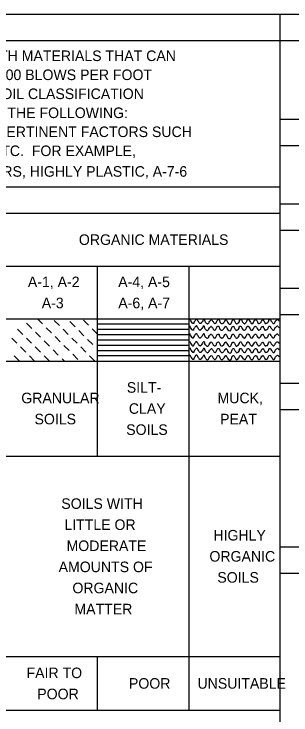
# Model space of a CAD drawing. Extents: x 278618 to 280654, y 171155 to 171855.
# Drawn here: x 280500.95 to 280512.35, y 171592.9 to 171621.7 of the extents above; entities that cross this region are included whole.
import ezdxf

# ---------------------------------------------------------------- set-up
doc = ezdxf.new("R2010")
doc.units = 0
doc.layers.add('Geotech Sheets and Borders Cell', color=7, linetype='Continuous')

msp = doc.modelspace()

# ---------------------------------------------------------------- linework, layer by layer
at = {"layer": 'Geotech Sheets and Borders Cell'}
for p, q in [((280474.148, 171621.702), (280624.148, 171621.702)), ((280511.888, 171621.702), (280511.888, 171541.488)), ((280474.148, 171620.618), (280624.148, 171620.618)), ((280549.148, 171617.364), (280511.888, 171617.364)), ((280549.148, 171616.28), (280511.888, 171616.28)), ((280474.148, 171614.6), (280511.888, 171614.6)), ((280549.148, 171613.894), (280511.888, 171613.894)), ((280474.148, 171613.515), (280511.888, 171613.515)), ((280549.148, 171612.809), (280511.888, 171612.809)), ((280474.148, 171611.346), (280511.888, 171611.346)), ((280504.384, 171603.538), (280504.384, 171611.346)), ((280508.158, 171593.093), (280508.158, 171611.346)), ((280549.148, 171610.423), (280511.888, 171610.423)), ((280549.148, 171609.339), (280511.888, 171609.339)), ((280474.148, 171609.177), (280511.888, 171609.177)), ((280501.677, 171608.782), (280501.464, 171608.995)), ((280501.907, 171609.177), (280502.119, 171608.965)), ((280502.813, 171608.899), (280502.601, 171609.112)), ((280503.247, 171609.06), (280503.46, 171608.847)), ((280504.015, 171608.912), (280503.802, 171609.125)), ((280501.308, 171608.535), (280501.095, 171608.748)), ((280502.271, 171608.813), (280502.483, 171608.6)), ((280503.178, 171608.535), (280502.965, 171608.748)), ((280503.611, 171608.696), (280503.824, 171608.483)), ((280504.379, 171608.548), (280504.167, 171608.761)), ((280504.384, 171608.965), (280508.158, 171608.965)), ((280504.384, 171608.748), (280508.158, 171608.748)), ((280508.184, 171608.895), (280508.179, 171608.891)), ((280502.041, 171608.418), (280501.828, 171608.631)), ((280502.635, 171608.448), (280502.848, 171608.236)), ((280504.384, 171608.531), (280508.158, 171608.531)), ((280508.184, 171608.574), (280508.179, 171608.57)), ((280501.065, 171608.171), (280500.852, 171608.383)), ((280501.672, 171608.171), (280501.46, 171608.383)), ((280502.193, 171608.266), (280502.405, 171608.054)), ((280503.542, 171608.171), (280503.329, 171608.383)), ((280503.976, 171608.331), (280504.188, 171608.119)), ((280504.384, 171608.314), (280508.158, 171608.314)), ((280508.188, 171608.249), (280508.184, 171608.244)), ((280501.429, 171607.806), (280501.217, 171608.019)), ((280502.037, 171607.806), (280501.824, 171608.019)), ((280502.557, 171607.902), (280502.77, 171607.689)), ((280503, 171608.084), (280503.212, 171607.871)), ((280503.906, 171607.806), (280503.694, 171608.019)), ((280504.384, 171608.097), (280508.158, 171608.097)), ((280504.384, 171607.88), (280508.158, 171607.88)), ((280508.197, 171607.98), (280508.192, 171607.975)), ((280501.16, 171607.446), (280500.948, 171607.659)), ((280501.794, 171607.442), (280501.581, 171607.654)), ((280502.401, 171607.442), (280502.188, 171607.654)), ((280502.922, 171607.537), (280503.021, 171607.442)), ((280503.364, 171607.72), (280503.577, 171607.507)), ((280504.271, 171607.442), (280504.058, 171607.654)), ((280504.384, 171607.663), (280508.158, 171607.663)), ((280508.162, 171607.62), (280508.158, 171607.624)), ((280508.166, 171607.663), (280508.162, 171607.659)), ((280508.192, 171607.694), (280508.188, 171607.689)), ((280474.148, 171607.442), (280511.888, 171607.442)), ((280549.148, 171606.519), (280511.888, 171606.519)), ((280549.148, 171605.435), (280511.888, 171605.435)), ((280474.148, 171603.538), (280511.888, 171603.538)), ((280549.148, 171599.795), (280511.888, 171599.795)), ((280549.148, 171598.711), (280511.888, 171598.711)), ((280474.148, 171595.296), (280511.888, 171595.296)), ((280504.384, 171593.093), (280504.384, 171595.296)), ((280474.148, 171593.093), (280511.888, 171593.093))]:
    msp.add_line(p, q, dxfattribs=at)
for points in [[(280508.86, 171608.999), (280508.834, 171609.034), (280508.804, 171609.108), (280508.787, 171609.151), (280508.769, 171609.155), (280508.748, 171609.142), (280508.717, 171609.095), (280508.656, 171609.008), (280508.635, 171608.986), (280508.609, 171608.978), (280508.591, 171608.986), (280508.574, 171609.008), (280508.5, 171609.129), (280508.483, 171609.151), (280508.474, 171609.155), (280508.453, 171609.155), (280508.427, 171609.138), (280508.392, 171609.082), (280508.348, 171609.008), (280508.344, 171608.986), (280508.318, 171608.978), (280508.296, 171608.991), (280508.283, 171609.017), (280508.231, 171609.095), (280508.192, 171609.164)], [(280508.865, 171608.999), (280508.895, 171608.973), (280508.956, 171608.995), (280508.986, 171609.043), (280509.047, 171609.125), (280509.073, 171609.147), (280509.108, 171609.112), (280509.138, 171609.06), (280509.173, 171609.008), (280509.207, 171608.982), (280509.251, 171608.995), (280509.285, 171609.047), (280509.351, 171609.142), (280509.385, 171609.142), (280509.411, 171609.099), (280509.481, 171608.986), (280509.515, 171608.982), (280509.55, 171608.995), (280509.65, 171609.125), (280509.676, 171609.147), (280509.689, 171609.125), (280509.715, 171609.086), (280509.767, 171608.995), (280509.854, 171608.96), (280509.884, 171608.986), (280509.945, 171609.121), (280509.993, 171609.142), (280510.01, 171609.121), (280510.071, 171609.017), (280510.105, 171608.973), (280510.162, 171608.995), (280510.222, 171609.069), (280510.257, 171609.142), (280510.288, 171609.147), (280510.322, 171609.108), (280510.374, 171609.017), (280510.422, 171608.986), (280510.452, 171608.973), (280510.496, 171609.03), (280510.535, 171609.086), (280510.561, 171609.142), (280510.6, 171609.147), (280510.622, 171609.125), (280510.678, 171609.034), (280510.713, 171608.986), (280510.773, 171608.986), (280510.825, 171609.073), (280510.878, 171609.134), (280510.895, 171609.147), (280510.938, 171609.112), (280510.969, 171609.047), (280511.021, 171608.986), (280511.064, 171608.995), (280511.116, 171609.043), (280511.168, 171609.125), (280511.19, 171609.134), (280511.203, 171609.142), (280511.22, 171609.112), (280511.242, 171609.073), (280511.311, 171608.986), (280511.329, 171608.995), (280511.359, 171608.995), (280511.433, 171609.108), (280511.459, 171609.147), (280511.511, 171609.142), (280511.524, 171609.099), (280511.572, 171609.043), (280511.619, 171608.986), (280511.65, 171608.986), (280511.684, 171609.021), (280511.715, 171609.095)], [(280511.715, 171609.095), (280511.762, 171609.134), (280511.802, 171609.155), (280511.836, 171609.125), (280511.862, 171609.086)], [(280508.847, 171608.726), (280508.821, 171608.761), (280508.791, 171608.834), (280508.774, 171608.878), (280508.756, 171608.882), (280508.735, 171608.869), (280508.704, 171608.821), (280508.643, 171608.735), (280508.622, 171608.713), (280508.596, 171608.704), (280508.578, 171608.713), (280508.561, 171608.735), (280508.487, 171608.856), (280508.47, 171608.878), (280508.461, 171608.882), (280508.44, 171608.882), (280508.414, 171608.865), (280508.379, 171608.808), (280508.335, 171608.735), (280508.331, 171608.713), (280508.305, 171608.704), (280508.283, 171608.717), (280508.27, 171608.743), (280508.218, 171608.821), (280508.179, 171608.891)], [(280508.852, 171608.726), (280508.882, 171608.7), (280508.943, 171608.722), (280508.973, 171608.769), (280509.034, 171608.852), (280509.06, 171608.873), (280509.095, 171608.839), (280509.125, 171608.787), (280509.16, 171608.735), (280509.194, 171608.709), (280509.238, 171608.722), (280509.272, 171608.774), (280509.338, 171608.869), (280509.372, 171608.869), (280509.398, 171608.826), (280509.468, 171608.713), (280509.502, 171608.709), (280509.537, 171608.722), (280509.637, 171608.852), (280509.663, 171608.873), (280509.676, 171608.852), (280509.702, 171608.813), (280509.754, 171608.722), (280509.841, 171608.687), (280509.871, 171608.713), (280509.932, 171608.847), (280509.98, 171608.869), (280509.997, 171608.847), (280510.058, 171608.743), (280510.092, 171608.7), (280510.149, 171608.722), (280510.209, 171608.795), (280510.244, 171608.869), (280510.275, 171608.873), (280510.309, 171608.834), (280510.361, 171608.743), (280510.409, 171608.713), (280510.439, 171608.7), (280510.483, 171608.756), (280510.522, 171608.813), (280510.548, 171608.869), (280510.587, 171608.873), (280510.609, 171608.852), (280510.665, 171608.761), (280510.7, 171608.713), (280510.76, 171608.713), (280510.812, 171608.8), (280510.864, 171608.86), (280510.882, 171608.873), (280510.925, 171608.839), (280510.956, 171608.774), (280511.008, 171608.713), (280511.051, 171608.722), (280511.103, 171608.769), (280511.155, 171608.852), (280511.177, 171608.86), (280511.19, 171608.869), (280511.207, 171608.839), (280511.229, 171608.8), (280511.298, 171608.713), (280511.316, 171608.722), (280511.346, 171608.722), (280511.42, 171608.834), (280511.446, 171608.873), (280511.498, 171608.869), (280511.511, 171608.826), (280511.559, 171608.769), (280511.606, 171608.713), (280511.637, 171608.713), (280511.671, 171608.748), (280511.702, 171608.821)], [(280511.702, 171608.821), (280511.749, 171608.86), (280511.788, 171608.882), (280511.823, 171608.852), (280511.849, 171608.813)], [(280508.847, 171608.405), (280508.821, 171608.44), (280508.791, 171608.513), (280508.774, 171608.557), (280508.756, 171608.561), (280508.735, 171608.548), (280508.704, 171608.5), (280508.643, 171608.414), (280508.622, 171608.392), (280508.596, 171608.383), (280508.578, 171608.392), (280508.561, 171608.414), (280508.487, 171608.535), (280508.47, 171608.557), (280508.461, 171608.561), (280508.44, 171608.561), (280508.414, 171608.544), (280508.379, 171608.487), (280508.335, 171608.414), (280508.331, 171608.392), (280508.305, 171608.383), (280508.283, 171608.396), (280508.27, 171608.422), (280508.218, 171608.5), (280508.179, 171608.57)], [(280508.852, 171608.405), (280508.882, 171608.379), (280508.943, 171608.401), (280508.973, 171608.448), (280509.034, 171608.531), (280509.06, 171608.552), (280509.095, 171608.518), (280509.125, 171608.466), (280509.16, 171608.414), (280509.194, 171608.388), (280509.238, 171608.401), (280509.272, 171608.453), (280509.338, 171608.548), (280509.372, 171608.548), (280509.398, 171608.505), (280509.468, 171608.392), (280509.502, 171608.388), (280509.537, 171608.401), (280509.637, 171608.531), (280509.663, 171608.552), (280509.676, 171608.531), (280509.702, 171608.492), (280509.754, 171608.401), (280509.841, 171608.366), (280509.871, 171608.392), (280509.932, 171608.526), (280509.98, 171608.548), (280509.997, 171608.526), (280510.058, 171608.422), (280510.092, 171608.379), (280510.149, 171608.401), (280510.209, 171608.474), (280510.244, 171608.548), (280510.275, 171608.552), (280510.309, 171608.513), (280510.361, 171608.422), (280510.409, 171608.392), (280510.439, 171608.379), (280510.483, 171608.435), (280510.522, 171608.492), (280510.548, 171608.548), (280510.587, 171608.552), (280510.609, 171608.531), (280510.665, 171608.44), (280510.7, 171608.392), (280510.76, 171608.392), (280510.812, 171608.479), (280510.864, 171608.539), (280510.882, 171608.552), (280510.925, 171608.518), (280510.956, 171608.453), (280511.008, 171608.392), (280511.051, 171608.401), (280511.103, 171608.448), (280511.155, 171608.531), (280511.177, 171608.539), (280511.19, 171608.548), (280511.207, 171608.518), (280511.229, 171608.479), (280511.298, 171608.392), (280511.316, 171608.401), (280511.346, 171608.401), (280511.42, 171608.513), (280511.446, 171608.552), (280511.498, 171608.548), (280511.511, 171608.505), (280511.559, 171608.448), (280511.606, 171608.392), (280511.637, 171608.392), (280511.671, 171608.427), (280511.702, 171608.5)], [(280511.702, 171608.5), (280511.749, 171608.539), (280511.788, 171608.561), (280511.823, 171608.531), (280511.849, 171608.492)], [(280508.852, 171608.08), (280508.826, 171608.114), (280508.795, 171608.188), (280508.778, 171608.231), (280508.761, 171608.236), (280508.739, 171608.223), (280508.709, 171608.175), (280508.648, 171608.088), (280508.626, 171608.067), (280508.6, 171608.058), (280508.583, 171608.067), (280508.565, 171608.088), (280508.492, 171608.21), (280508.474, 171608.231), (280508.466, 171608.236), (280508.444, 171608.236), (280508.418, 171608.218), (280508.383, 171608.162), (280508.34, 171608.088), (280508.335, 171608.067), (280508.309, 171608.058), (280508.288, 171608.071), (280508.275, 171608.097), (280508.223, 171608.175), (280508.184, 171608.244)], [(280508.856, 171608.08), (280508.886, 171608.054), (280508.947, 171608.075), (280508.977, 171608.123), (280509.038, 171608.205), (280509.064, 171608.227), (280509.099, 171608.192), (280509.129, 171608.14), (280509.164, 171608.088), (280509.199, 171608.062), (280509.242, 171608.075), (280509.277, 171608.127), (280509.342, 171608.223), (280509.377, 171608.223), (280509.403, 171608.179), (280509.472, 171608.067), (280509.507, 171608.062), (280509.541, 171608.075), (280509.641, 171608.205), (280509.667, 171608.227), (280509.68, 171608.205), (280509.706, 171608.166), (280509.758, 171608.075), (280509.845, 171608.041), (280509.875, 171608.067), (280509.936, 171608.201), (280509.984, 171608.223), (280510.001, 171608.201), (280510.062, 171608.097), (280510.097, 171608.054), (280510.153, 171608.075), (280510.214, 171608.149), (280510.249, 171608.223), (280510.279, 171608.227), (280510.314, 171608.188), (280510.366, 171608.097), (280510.413, 171608.067), (280510.444, 171608.054), (280510.487, 171608.11), (280510.526, 171608.166), (280510.552, 171608.223), (280510.591, 171608.227), (280510.613, 171608.205), (280510.669, 171608.114), (280510.704, 171608.067), (280510.765, 171608.067), (280510.817, 171608.153), (280510.869, 171608.214), (280510.886, 171608.227), (280510.93, 171608.192), (280510.96, 171608.127), (280511.012, 171608.067), (280511.055, 171608.075), (280511.107, 171608.123), (280511.159, 171608.205), (280511.181, 171608.214), (280511.194, 171608.223), (280511.212, 171608.192), (280511.233, 171608.153), (280511.303, 171608.067), (280511.32, 171608.075), (280511.35, 171608.075), (280511.424, 171608.188), (280511.45, 171608.227), (280511.502, 171608.223), (280511.515, 171608.179), (280511.563, 171608.123), (280511.611, 171608.067), (280511.641, 171608.067), (280511.676, 171608.101), (280511.706, 171608.175)], [(280511.706, 171608.175), (280511.754, 171608.214), (280511.793, 171608.236), (280511.828, 171608.205), (280511.854, 171608.166)], [(280508.86, 171607.811), (280508.834, 171607.845), (280508.804, 171607.919), (280508.787, 171607.962), (280508.769, 171607.967), (280508.748, 171607.954), (280508.717, 171607.906), (280508.656, 171607.819), (280508.635, 171607.798), (280508.609, 171607.789), (280508.591, 171607.798), (280508.574, 171607.819), (280508.5, 171607.941), (280508.483, 171607.962), (280508.474, 171607.967), (280508.453, 171607.967), (280508.427, 171607.949), (280508.392, 171607.893), (280508.348, 171607.819), (280508.344, 171607.798), (280508.318, 171607.789), (280508.296, 171607.802), (280508.283, 171607.828), (280508.231, 171607.906), (280508.192, 171607.975)], [(280508.865, 171607.811), (280508.895, 171607.785), (280508.956, 171607.806), (280508.986, 171607.854), (280509.047, 171607.936), (280509.073, 171607.958), (280509.108, 171607.923), (280509.138, 171607.871), (280509.173, 171607.819), (280509.207, 171607.793), (280509.251, 171607.806), (280509.285, 171607.858), (280509.351, 171607.954), (280509.385, 171607.954), (280509.411, 171607.91), (280509.481, 171607.798), (280509.515, 171607.793), (280509.55, 171607.806), (280509.65, 171607.936), (280509.676, 171607.958), (280509.689, 171607.936), (280509.715, 171607.897), (280509.767, 171607.806), (280509.854, 171607.772), (280509.884, 171607.798), (280509.945, 171607.932), (280509.993, 171607.954), (280510.01, 171607.932), (280510.071, 171607.828), (280510.105, 171607.785), (280510.162, 171607.806), (280510.222, 171607.88), (280510.257, 171607.954), (280510.288, 171607.958), (280510.322, 171607.919), (280510.374, 171607.828), (280510.422, 171607.798), (280510.452, 171607.785), (280510.496, 171607.841), (280510.535, 171607.897), (280510.561, 171607.954), (280510.6, 171607.958), (280510.622, 171607.936), (280510.678, 171607.845), (280510.713, 171607.798), (280510.773, 171607.798), (280510.825, 171607.884), (280510.878, 171607.945), (280510.895, 171607.958), (280510.938, 171607.923), (280510.969, 171607.858), (280511.021, 171607.798), (280511.064, 171607.806), (280511.116, 171607.854), (280511.168, 171607.936), (280511.19, 171607.945), (280511.203, 171607.954), (280511.22, 171607.923), (280511.242, 171607.884), (280511.311, 171607.798), (280511.329, 171607.806), (280511.359, 171607.806), (280511.433, 171607.919), (280511.459, 171607.958), (280511.511, 171607.954), (280511.524, 171607.91), (280511.572, 171607.854), (280511.619, 171607.798), (280511.65, 171607.798), (280511.684, 171607.832), (280511.715, 171607.906)], [(280511.715, 171607.906), (280511.762, 171607.945), (280511.802, 171607.967), (280511.836, 171607.936), (280511.862, 171607.897)], [(280508.856, 171607.524), (280508.83, 171607.559), (280508.8, 171607.633), (280508.782, 171607.676), (280508.765, 171607.68), (280508.743, 171607.667), (280508.713, 171607.62), (280508.652, 171607.533), (280508.63, 171607.511), (280508.604, 171607.503), (280508.587, 171607.511), (280508.57, 171607.533), (280508.496, 171607.654), (280508.479, 171607.676), (280508.47, 171607.68), (280508.448, 171607.68), (280508.422, 171607.663), (280508.388, 171607.607), (280508.344, 171607.533), (280508.34, 171607.511), (280508.314, 171607.503), (280508.292, 171607.516), (280508.279, 171607.542), (280508.227, 171607.62), (280508.188, 171607.689)], [(280508.86, 171607.524), (280508.891, 171607.498), (280508.951, 171607.52), (280508.982, 171607.568), (280509.043, 171607.65), (280509.069, 171607.672), (280509.103, 171607.637), (280509.134, 171607.585), (280509.168, 171607.533), (280509.203, 171607.507), (280509.246, 171607.52), (280509.281, 171607.572), (280509.346, 171607.667), (280509.381, 171607.667), (280509.407, 171607.624), (280509.476, 171607.511), (280509.511, 171607.507), (280509.546, 171607.52), (280509.646, 171607.65), (280509.672, 171607.672), (280509.685, 171607.65), (280509.711, 171607.611), (280509.763, 171607.52), (280509.849, 171607.485), (280509.88, 171607.511), (280509.941, 171607.646), (280509.988, 171607.667), (280510.006, 171607.646), (280510.066, 171607.542), (280510.101, 171607.498), (280510.157, 171607.52), (280510.218, 171607.594), (280510.253, 171607.667), (280510.283, 171607.672), (280510.318, 171607.633), (280510.37, 171607.542), (280510.418, 171607.511), (280510.448, 171607.498), (280510.491, 171607.555), (280510.53, 171607.611), (280510.557, 171607.667), (280510.596, 171607.672), (280510.617, 171607.65), (280510.674, 171607.559), (280510.708, 171607.511), (280510.769, 171607.511), (280510.821, 171607.598), (280510.873, 171607.659), (280510.891, 171607.672), (280510.934, 171607.637), (280510.964, 171607.572), (280511.016, 171607.511), (280511.06, 171607.52), (280511.112, 171607.568), (280511.164, 171607.65), (280511.186, 171607.659), (280511.199, 171607.667), (280511.216, 171607.637), (280511.238, 171607.598), (280511.307, 171607.511), (280511.324, 171607.52), (280511.355, 171607.52), (280511.428, 171607.633), (280511.454, 171607.672), (280511.507, 171607.667), (280511.52, 171607.624), (280511.567, 171607.568), (280511.615, 171607.511), (280511.645, 171607.511), (280511.68, 171607.546), (280511.71, 171607.62)], [(280511.71, 171607.62), (280511.758, 171607.659), (280511.797, 171607.68), (280511.832, 171607.65), (280511.858, 171607.611)]]:
    msp.add_spline(points, degree=3, dxfattribs=at)

# ---------------------------------------------------------------- texts
for s, height, p in [('SOIL IS CONSIDERED UNCONSOLIDATED, SEMI-CONSOLIDATED, OR WEATHERED EARTH MATERIALS THAT CAN', 0.43381, (280475.768, 171619.769)), ('BE PENETRATED WITH A CONTINUOUS FLIGHT POWER AUGER AND YIELD LESS THAN 100 BLOWS PER FOOT', 0.43381, (280475.622, 171618.988)), ('ACCORDING TO THE STANDARD PENETRATION TEST (AASHTO T 206, ASTM D1586).  SOIL CLASSIFICATION', 0.43381, (280476.057, 171618.207)), ('IS BASED ON THE AASHTO SYSTEM.  BASIC DESCRIPTIONS GENERALLY INCLUDE THE FOLLOWING:', 0.43381, (280477.304, 171617.426)), ('CONSISTENCY, COLOR, TEXTURE, MOISTURE, AASHTO CLASSIFICATION, AND OTHER PERTINENT FACTORS SUCH ', 0.43381, (280475.716, 171616.646)), ('AS MINERALOGICAL COMPOSITION, ANGULARITY, STRUCTURE, PLASTICITY, ETC.  FOR EXAMPLE,', 0.43381, (280478.149, 171615.865)), ('VERY STIFF, GRAY, SILTY CLAY, MOIST WITH INTERBEDDED FINE SAND LAYERS, HIGHLY PLASTIC, A-7-6', 0.43381, (280478.516, 171615.016)), ('ORGANIC MATERIALS', 0.43381, (280503.617, 171612.214)), ('A-1, A-2', 0.4338, (280501.517, 171610.478)), ('A-4, A-5', 0.4338, (280505.236, 171610.478)), ('A-3', 0.4338, (280502.088, 171609.612)), ('A-6, A-7', 0.4338, (280505.239, 171609.612)), ('SILT-', 0.4338, (280505.59, 171606.14)), ('GRANULAR', 0.4338, (280501.246, 171605.707)), ('MUCK,', 0.4338, (280509.324, 171605.707)), ('CLAY', 0.4338, (280505.673, 171605.273)), ('SOILS', 0.4338, (280501.791, 171604.84)), ('PEAT', 0.4338, (280509.429, 171604.84)), ('SOILS', 0.4338, (280505.565, 171604.407)), ('SOILS WITH', 0.4338, (280502.894, 171601.367)), ('LITTLE OR', 0.4338, (280503.02, 171600.501)), ('HIGHLY', 0.4338, (280509.154, 171600.067)), ('MODERATE', 0.4338, (280503.109, 171599.634)), ('ORGANIC', 0.4338, (280508.991, 171599.2)), ('AMOUNTS OF', 0.4338, (280502.783, 171598.767)), ('SOILS', 0.4338, (280509.317, 171598.334)), ('ORGANIC', 0.4338, (280503.351, 171597.9)), ('MATTER', 0.4338, (280503.433, 171597.033)), ('FAIR TO', 0.4338, (280501.462, 171594.411)), ('POOR', 0.4338, (280505.678, 171593.978)), ('UNSUITABLE', 0.4338, (280508.499, 171593.978)), ('POOR', 0.4338, (280501.904, 171593.544))]:
    msp.add_text(s, height=height, dxfattribs=at).set_placement(p)

doc.saveas('drawing.dxf')
